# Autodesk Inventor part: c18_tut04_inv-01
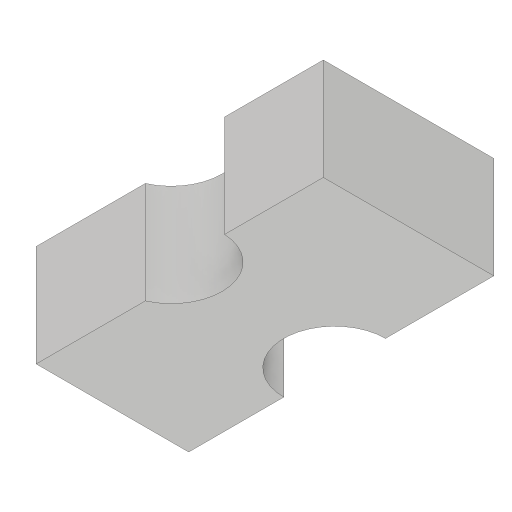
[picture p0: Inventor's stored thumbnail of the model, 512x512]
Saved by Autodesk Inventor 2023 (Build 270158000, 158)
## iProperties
Created: 2017-06
Part Number: c18_tut04_inv-01
Material: Generic
Document SubType Name: Modeling
Designer: CADCIM 00
Density: 1 g/cm^3
Appearance: Default
Author: CADCIM 00
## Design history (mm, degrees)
derived "c18_tut04_inv.ipt"
feature "Solid1::c18_tut04_inv.ipt"
tag "TaggingFeature1"
body "Solid1"
other parameters: "d2" = 10, "d4" = 0, "d5" = 6, "RAD" = 10, "FILLET" = 6
